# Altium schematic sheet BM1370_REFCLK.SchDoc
size A4; SheetNumber: 8; SheetTotal: 15
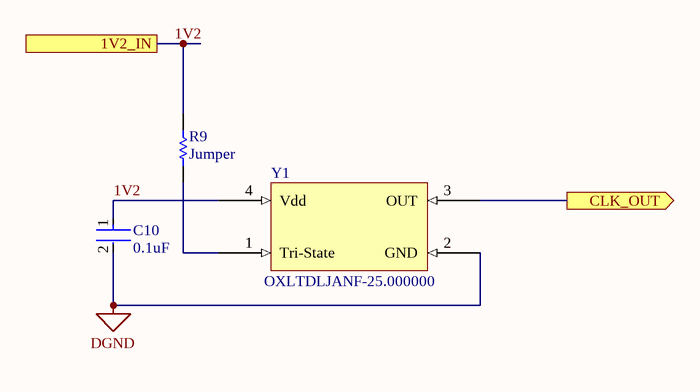
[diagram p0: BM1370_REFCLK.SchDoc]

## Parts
C10  value 0.1uF  [FP-CC0402-IPC_C]  (hidden comment: CC0402KRX7R7BB104)
R9  value Jumper  [FP-RK73Z1E-IPC_B]  (hidden comment: RK73Z1ETTP)
Y1  OXLTDLJANF-25.000000  [OXLTDLJANF-25.000000-Footprint-1]

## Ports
1V2_IN, CLK_OUT (out)

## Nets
DGND: C10.2 Y1.2(GND)
1V2: C10.1 R9.2 Y1.4(Vdd) ; port 1V2_IN
CLK_OUT: Y1.3(OUT) ; port CLK_OUT
NetR9_1: R9.1 Y1.1(Tri-State)

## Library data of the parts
C10 = CMP-001-00094-1: Multilayer Ceramic Capacitor, 0.1 uF, 25 V, ± 10%, X7R, 0402 [1005 Metric]; Rating: 16V; Reel Size: 8mm; Vendor: TTI
R9 = CMP-x00147-1: Metal Glaze/thick Film, 0ohm, Surface Mount, 0402
Y1 = CMP-x00169-1: Xtal Osc Xo 25MHZ 1.2V Cmos SMD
